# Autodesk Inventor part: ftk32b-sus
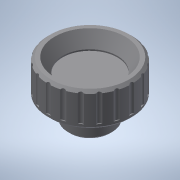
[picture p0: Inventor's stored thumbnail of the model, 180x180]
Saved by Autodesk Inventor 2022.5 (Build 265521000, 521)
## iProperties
Created: 2016-12
Part Number: ftk32b-sus
Material: 一般
Document SubType Name: Modeling
Designer: imaocorp
Density: 1 g/cm^3
Appearance: 既定
Author: imaocorp
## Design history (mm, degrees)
node "ftk32b-sus.x_t1"
node "ftk32b-sus"
node "Base1"
